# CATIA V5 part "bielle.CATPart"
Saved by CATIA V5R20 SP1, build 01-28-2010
Part number: bielleaube
Bounding box of the stored display mesh (mm): x 58 to 87, y 0 to 5, z 22.5 to 47.5
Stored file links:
  E:\EDELI\gcausse\Edeli_2012_613_gcausse\bielle.CATPart
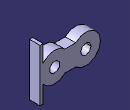
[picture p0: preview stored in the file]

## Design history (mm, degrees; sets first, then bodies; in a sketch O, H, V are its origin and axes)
Parameters
  long = 0.015
  diamtrou = 0.005
Body1 (main body)
  Sketch1 on zx-plane, origin (0, 0, 0), H (-1, 0, 0), V (0, 0, 1)
    line L1 (-69.899, 40) -> (-75.101, 40)
    line L2 (-69.899, 30) -> (-75.101, 30)
    arc A1 centre (-65, 35) radius 7 from (-69.899, 40) to (-69.899, 30) cw
    point P5 (-65, 35)
    point P6 (-60.101, 30)
    arc A2 centre (-80, 35) radius 7 from (-75.101, 40) to (-75.101, 30) ccw
    point P7 (-80, 35)
    circle A3 centre (-65, 35) radius 2.5
    distance P7 L1 = 5
    distance P5 L2 = 5
    distance L2 L1 = 10
    radius A1 = 7
    radius A2 = 7
    distance P5 P7 = 15 {= long}
    radius A3 = 2.5
    horizontal: L1 H, L2 H
    coincidence: A1 P6, P6 L2
  Pad1: profile Sketch1, direction (0, 1, 0), length 5
  Sketch2 on start face of Pad1, origin (77.4564, 0, 36.1809), H (1, 0, 0), V (0, 0, 1)
    point P1 (2.5436, -1.1809)
    reference projected arc E1 centre (2.5436, -1.1809) radius 7 from (-2.3554, -6.1809) to (-2.3554, 3.8191) ccw from edge [start face of Pad1 | face of Pad1 from Sketch1.A2]
    reference projected arc E2 centre (2.5436, -1.1809) radius 7 from (-2.3554, -6.1809) to (-2.3554, 3.8191) ccw from edge [start face of Pad1 | face of Pad1 from Sketch1.A2]
    radius E2 = 7 (reference)
    concentricity: P1 E1
  Hole1: placed by Sketch2, at (80, 0, 35) direction (0, 1, 0), diameter 5, depth 10
  Sketch3 on start face of Pad1, origin (0, 0, 0), H (1, 0, 0), V (0, 0, 1)
    line L1 (85.5, 47.5) -> (87, 47.5)
    line L2 (87, 47.5) -> (87, 22.5)
    line L3 (87, 22.5) -> (85.5, 22.5)
    line L4 (85.5, 22.5) -> (85.5, 47.5)
    reference projected arc E1 centre (80, 35) radius 7 from (75.101, 30) to (75.101, 40) ccw from edge [start face of Pad1 | face of Pad1 from Sketch1.A2]
    reference projected circle E2 centre (80, 35) radius 2.5 from edge [face of Hole1 | start face of Pad1]
    distance L2 L4 = 1.5
    length L2 = 25
    length L4 = 25
    distance L3 E1 = 5.5
    distance E2 L4 = 3
    horizontal: L3 H
    vertical: L4 V, L2 V
  Pad2: profile Sketch3, direction (0, -1, 0), length -8, opposite side length -3
  Fillet1: radius 2, on edge [face of Pad2 from Sketch3.L1 | start face of Pad2]; edge [end face of Pad2 | face of Pad2 from Sketch3.L1]; edge [face of Pad2 from Sketch3.L3 | start face of Pad2]; edge [end face of Pad2 | face of Pad2 from Sketch3.L3]
  Sketch4 on face of Pad2 from Sketch3.L4, origin (85.5, 0, 0), H (0, -1, 0), V (0, 0, 1)
    line L1 (-25, 50) -> (-5, 50)
    line L2 (-5, 50) -> (-5, 20)
    line L3 (-5, 20) -> (-25, 20)
    line L4 (-25, 20) -> (-25, 50)
    reference projected line E1 (-5, 39.3301) -> (-5, 30.6699) from edge [face of Pad2 from Sketch3.L4 | end face of Pad1]
    horizontal: L1 H, L3 H
    vertical: L2 V, L4 V
    coincidence: L2 E1
  Pocket1: profile Sketch4, direction (1, 0, 0), length 2
  Sketch5 on face of Pad2 from Sketch3.L4, origin (85.5, 0, 0), H (0, -1, 0), V (0, 0, 1)
    line L1 (0, 50) -> (10, 50)
    line L2 (10, 50) -> (10, 20)
    line L3 (10, 20) -> (0, 20)
    line L4 (0, 20) -> (0, 50)
    horizontal: L1 H, L3 H
    vertical: L2 V, L4 V
  Pocket2: profile Sketch5, direction (1, 0, 0), length 2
